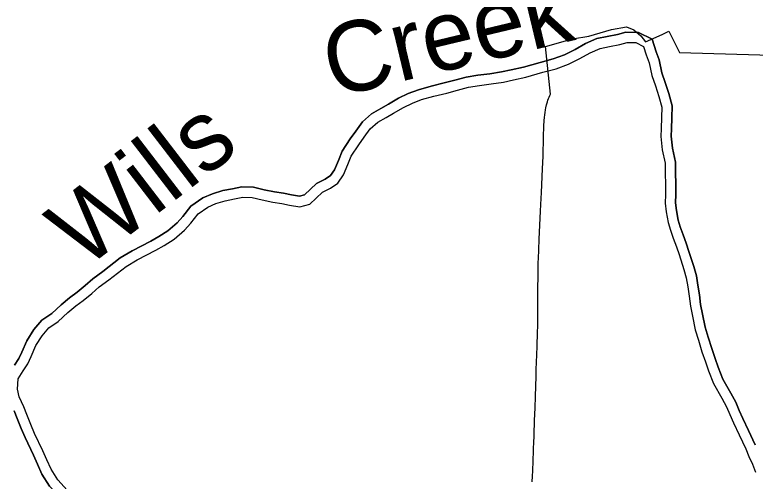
# Model space of a CAD drawing. Extents: x -12.1 to 34, y 0 to 22.
# Drawn here: x -7.82 to -6.886, y 11.53 to 12.119 of the extents above; entities that cross this region are included whole.
import ezdxf

# ---------------------------------------------------------------- set-up
doc = ezdxf.new("R2010")
doc.units = 0
for name, color, linetype in [('GM_X_Corporation', 7, 'Continuous'), ('GM_X_Major_River', 7, 'Continuous'), ('GM_X_Major_River_Text', 7, 'Continuous')]:
    doc.layers.add(name, color=color, linetype=linetype)

msp = doc.modelspace()

# ---------------------------------------------------------------- linework, layer by layer
at = {"layer": 'GM_X_Corporation'}
msp.add_lwpolyline([(-7.16732, 11.52924), (-7.167, 11.53616), (-7.16672, 11.54311), (-7.16578, 11.56813), (-7.16563, 11.57274), (-7.16545, 11.57691), (-7.16492, 11.5884), (-7.16427, 11.60647), (-7.1638, 11.62267), (-7.16323, 11.63688), (-7.16277, 11.6499), (-7.16253, 11.66208), (-7.16231, 11.67109), (-7.16192, 11.68019), (-7.16161, 11.68928), (-7.16122, 11.70038), (-7.16053, 11.71756), (-7.16022, 11.72604), (-7.16015, 11.73375), (-7.16022, 11.74253), (-7.16015, 11.75718), (-7.16007, 11.77505), (-7.15992, 11.787), (-7.15984, 11.80049), (-7.15969, 11.80603), (-7.15961, 11.81104), (-7.15907, 11.82206), (-7.15853, 11.83532), (-7.15814, 11.84418), (-7.1568, 11.87071), (-7.15638, 11.87943), (-7.1557, 11.89451), (-7.15422, 11.92417), (-7.15367, 11.94038), (-7.15291, 11.96486), (-7.15253, 11.97795), (-7.15218, 11.98508), (-7.15189, 11.98909), (-7.15148, 11.99244), (-7.15102, 11.99544), (-7.15048, 11.99861), (-7.15002, 12.00115), (-7.14911, 12.00504), (-7.14813, 12.00882), (-7.14742, 12.01082), (-7.14672, 12.0129), (-7.14597, 12.01475), (-7.14513, 12.01675), (-7.14435, 12.01837), (-7.15047, 12.07857), (-7.11653, 12.08851), (-7.09596, 12.09167), (-7.06748, 12.10038), (-7.0485, 12.10355), (-7.039, 12.09959), (-7.03037, 12.09228), (-7.02446, 12.08466), (-7.00351, 12.09403), (-6.99495, 12.09787), (-6.98141, 12.07105), (-6.6626, 12.0617)], dxfattribs=at)
at = {"layer": 'GM_X_Major_River'}
for points in [[(-7.82074, 11.67635), (-7.81523, 11.68461), (-7.81151, 11.69283), (-7.8052, 11.70727), (-7.79611, 11.72134), (-7.78598, 11.73336), (-7.77368, 11.74172), (-7.76184, 11.75273), (-7.75134, 11.76151), (-7.74177, 11.76836), (-7.73141, 11.77686), (-7.72197, 11.78536), (-7.70928, 11.79459), (-7.68728, 11.81185), (-7.67214, 11.82072), (-7.64881, 11.83299), (-7.63864, 11.83887), (-7.62695, 11.84615), (-7.6153, 11.85608), (-7.60812, 11.86402), (-7.59808, 11.87699), (-7.58298, 11.88753), (-7.57089, 11.89265), (-7.55789, 11.8967), (-7.54559, 11.89904), (-7.53363, 11.90153), (-7.51898, 11.90119), (-7.50543, 11.8978), (-7.49256, 11.89518), (-7.48119, 11.89348), (-7.47105, 11.89137), (-7.46113, 11.88957), (-7.45468, 11.89146), (-7.43941, 11.90565), (-7.42863, 11.91116), (-7.42185, 11.91576), (-7.41696, 11.92298), (-7.41192, 11.9349), (-7.40729, 11.94636), (-7.39694, 11.96198), (-7.38986, 11.97172), (-7.38164, 11.98366), (-7.36994, 11.99381), (-7.35822, 12.00058), (-7.34872, 12.00597), (-7.33598, 12.01339), (-7.32367, 12.01929), (-7.31096, 12.02403), (-7.29468, 12.02861), (-7.27836, 12.03265), (-7.26502, 12.03627), (-7.25057, 12.0401), (-7.23591, 12.04247), (-7.22093, 12.04437), (-7.206, 12.04652), (-7.19369, 12.04936), (-7.17847, 12.0526), (-7.1572, 12.05871), (-7.14107, 12.06296), (-7.12677, 12.0683), (-7.11322, 12.07505), (-7.10018, 12.08244), (-7.08567, 12.08863), (-7.07266, 12.09149), (-7.05992, 12.09401), (-7.04934, 12.09695), (-7.03308, 12.09656), (-7.01591, 12.08778), (-7.01112, 12.07218), (-7.00734, 12.0618), (-7.00365, 12.04565), (-6.99948, 12.03307), (-6.99502, 12.01925), (-6.99081, 12.00366), (-6.99111, 11.98849), (-6.99173, 11.97457), (-6.99198, 11.96563), (-6.99027, 11.95017), (-6.98646, 11.93283), (-6.98617, 11.89202)], [(-6.98617, 11.8918), (-6.98646, 11.93283), (-6.99027, 11.95017), (-6.99198, 11.96563), (-6.99173, 11.97457), (-6.99111, 11.98849), (-6.99081, 12.00366), (-6.99502, 12.01925), (-6.99948, 12.03307), (-7.00365, 12.04565), (-7.00734, 12.0618), (-7.01112, 12.07218), (-7.01591, 12.08778), (-7.03308, 12.09656), (-7.04934, 12.09695), (-7.05992, 12.09401), (-7.07266, 12.09149), (-7.08567, 12.08863), (-7.10018, 12.08244), (-7.11322, 12.07505), (-7.12677, 12.0683), (-7.14107, 12.06296), (-7.1572, 12.05871), (-7.17847, 12.0526), (-7.19369, 12.04936), (-7.206, 12.04652), (-7.22093, 12.04437), (-7.23591, 12.04247), (-7.25057, 12.0401), (-7.26502, 12.03627), (-7.27836, 12.03265), (-7.29468, 12.02861), (-7.31096, 12.02403), (-7.32367, 12.01929), (-7.33598, 12.01339), (-7.34872, 12.00597), (-7.35822, 12.00058), (-7.36994, 11.99381), (-7.38164, 11.98366), (-7.38986, 11.97172), (-7.39694, 11.96198), (-7.40729, 11.94636), (-7.41192, 11.9349), (-7.41696, 11.92298), (-7.42185, 11.91576), (-7.42863, 11.91116), (-7.43941, 11.90565), (-7.45468, 11.89146), (-7.46113, 11.88957), (-7.47105, 11.89137), (-7.48119, 11.89348), (-7.49256, 11.89518), (-7.50543, 11.8978), (-7.51898, 11.90119), (-7.53363, 11.90153), (-7.54559, 11.89904), (-7.55789, 11.8967), (-7.57089, 11.89265), (-7.58298, 11.88753), (-7.59808, 11.87699), (-7.60812, 11.86402), (-7.6153, 11.85608), (-7.62695, 11.84615), (-7.63864, 11.83887), (-7.64881, 11.83299), (-7.67214, 11.82072), (-7.68728, 11.81185), (-7.70928, 11.79459), (-7.72197, 11.78536), (-7.73141, 11.77686), (-7.74177, 11.76836), (-7.75134, 11.76151), (-7.76184, 11.75273), (-7.77368, 11.74172), (-7.78598, 11.73336), (-7.79611, 11.72134), (-7.8052, 11.70727), (-7.81151, 11.69283), (-7.81523, 11.68461), (-7.82074, 11.67635)], [(-7.75412, 11.51871), (-7.76591, 11.53178), (-7.7745, 11.54521), (-7.7799, 11.5569), (-7.78494, 11.56824), (-7.79536, 11.59019), (-7.80005, 11.60153), (-7.80509, 11.61393), (-7.80906, 11.62385), (-7.81482, 11.63624), (-7.81701, 11.64618), (-7.81604, 11.65898), (-7.80973, 11.66933), (-7.80377, 11.67825), (-7.79958, 11.68752), (-7.79366, 11.70107), (-7.78559, 11.71356), (-7.77716, 11.72357), (-7.76552, 11.73147), (-7.7532, 11.74293), (-7.74334, 11.75117), (-7.73382, 11.758), (-7.7229, 11.76696), (-7.71375, 11.7752), (-7.70141, 11.78417), (-7.67991, 11.80102), (-7.6658, 11.8093), (-7.6425, 11.82155), (-7.63192, 11.82766), (-7.61922, 11.83557), (-7.60618, 11.84668), (-7.5981, 11.85563), (-7.58897, 11.86742), (-7.57663, 11.87604), (-7.56638, 11.88037), (-7.55472, 11.88401), (-7.54304, 11.88623), (-7.53243, 11.88844), (-7.52073, 11.88816), (-7.50831, 11.88506), (-7.49483, 11.88231), (-7.48348, 11.88061), (-7.47355, 11.87855), (-7.46042, 11.87616), (-7.44804, 11.8798), (-7.43185, 11.89485), (-7.42197, 11.89989), (-7.41244, 11.90636), (-7.40543, 11.91671), (-7.39986, 11.9299), (-7.39568, 11.94024), (-7.38621, 11.95452), (-7.3792, 11.96417), (-7.37183, 11.97488), (-7.36232, 11.98313), (-7.35174, 11.98924), (-7.34221, 11.99464), (-7.32986, 12.00184), (-7.31856, 12.00725), (-7.3069, 12.0116), (-7.29134, 12.01598), (-7.27507, 12.02), (-7.26164, 12.02365), (-7.24784, 12.02731), (-7.23404, 12.02954), (-7.21917, 12.03143), (-7.2036, 12.03367), (-7.19086, 12.03661), (-7.1753, 12.03992), (-7.15373, 12.04611), (-7.13711, 12.0505), (-7.12156, 12.0563), (-7.10709, 12.06351), (-7.09438, 12.07071), (-7.08167, 12.07613), (-7.06999, 12.0787), (-7.0569, 12.08129), (-7.04771, 12.08384), (-7.03637, 12.08357), (-7.02677, 12.07866), (-7.0235, 12.06802), (-7.01989, 12.0581), (-7.01623, 12.04213), (-7.01189, 12.02901), (-7.00754, 12.01554), (-7.0039, 12.00206), (-7.00417, 11.98891), (-7.00478, 11.97505), (-7.00506, 11.96509), (-7.00317, 11.94805), (-6.99951, 11.93137), (-6.99923, 11.89193)], [(-6.99923, 11.89193), (-6.99951, 11.88091), (-6.99837, 11.8699), (-6.99579, 11.85642), (-6.99289, 11.84684), (-6.98928, 11.83656), (-6.9853, 11.82593), (-6.98205, 11.816), (-6.97589, 11.79721), (-6.97298, 11.78657), (-6.97113, 11.77521), (-6.96928, 11.7635), (-6.96777, 11.75107), (-6.9652, 11.7383), (-6.96189, 11.72091), (-6.95755, 11.70779), (-6.9532, 11.69326), (-6.94885, 11.6805), (-6.94488, 11.66915), (-6.93875, 11.65321), (-6.92799, 11.63481), (-6.92224, 11.62384), (-6.91792, 11.61392), (-6.91325, 11.60365), (-6.90605, 11.58842), (-6.89778, 11.57071), (-6.89382, 11.56115), (-6.8895, 11.55123), (-6.88553, 11.54131)], [(-6.88583, 11.57598), (-6.89424, 11.59397), (-6.9014, 11.60914), (-6.906, 11.61923), (-6.91046, 11.62948), (-6.91657, 11.64114), (-6.92694, 11.65889), (-6.93262, 11.67366), (-6.93651, 11.68476), (-6.94076, 11.69724), (-6.9451, 11.71172), (-6.94923, 11.7242), (-6.95239, 11.74081), (-6.95487, 11.75315), (-6.95634, 11.76531), (-6.95824, 11.77728), (-6.96021, 11.78935), (-6.96338, 11.80097), (-6.96964, 11.82007), (-6.97298, 11.83025), (-6.977, 11.84101), (-6.98048, 11.8509), (-6.98309, 11.85954), (-6.98544, 11.8718), (-6.98643, 11.88142), (-6.98617, 11.8918)], [(-6.98618, 11.8916), (-6.98643, 11.88142), (-6.98544, 11.8718), (-6.98309, 11.85954), (-6.98048, 11.8509), (-6.977, 11.84101), (-6.97298, 11.83025), (-6.96964, 11.82007), (-6.96338, 11.80097), (-6.96021, 11.78935), (-6.95824, 11.77728), (-6.95634, 11.76531), (-6.95487, 11.75315), (-6.95239, 11.74081), (-6.94923, 11.7242), (-6.9451, 11.71172), (-6.94076, 11.69724), (-6.93651, 11.68476), (-6.93262, 11.67366), (-6.92694, 11.65889), (-6.91657, 11.64114), (-6.91046, 11.62948), (-6.906, 11.61923), (-6.9014, 11.60914), (-6.89424, 11.59397), (-6.88583, 11.57598)], [(-7.69576, 11.4039), (-7.7023, 11.41594), (-7.70436, 11.43157), (-7.70686, 11.44025), (-7.71367, 11.45126), (-7.72282, 11.46498), (-7.73252, 11.47656), (-7.74353, 11.4885), (-7.75155, 11.4978), (-7.76357, 11.50969), (-7.77632, 11.52383), (-7.78598, 11.53893), (-7.79179, 11.55151), (-7.7968, 11.56278), (-7.8073, 11.58489), (-7.81213, 11.59658), (-7.8172, 11.60904), (-7.82105, 11.61867)], [(-7.82105, 11.61867), (-7.8172, 11.60904), (-7.81213, 11.59658), (-7.8073, 11.58489), (-7.7968, 11.56278), (-7.79179, 11.55151), (-7.78598, 11.53893), (-7.77632, 11.52383), (-7.76357, 11.50969), (-7.75155, 11.4978), (-7.74353, 11.4885), (-7.73252, 11.47656), (-7.72282, 11.46498), (-7.71367, 11.45126), (-7.70686, 11.44025), (-7.70436, 11.43157), (-7.7023, 11.41594), (-7.69268, 11.39822)]]:
    msp.add_lwpolyline(points, dxfattribs=at)

# ---------------------------------------------------------------- texts
at = {"layer": 'GM_X_Major_River_Text'}
for s, height, rotation, p in [('Creek', 0.08877, 13.44209, (-7.41902, 12.01379)), ('Wills', 0.088773, 37.52131, (-7.73304, 11.79599))]:
    msp.add_text(s, height=height, rotation=rotation, dxfattribs=at).set_placement(p)

doc.saveas('drawing.dxf')
